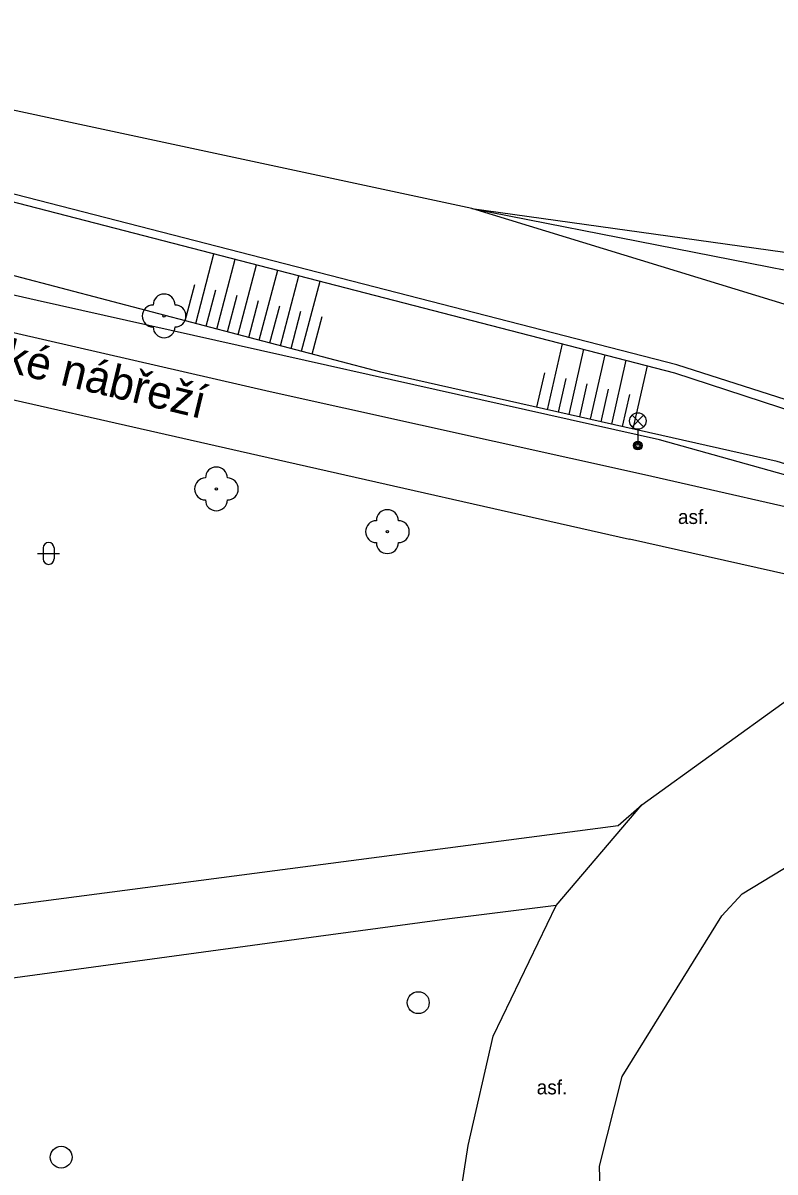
# Model space of a CAD drawing. Extents: x -598932 to -598196, y -1162207 to -1161504.
# Drawn here: x -598441.5 to -598407.2, y -1162126.2 to -1162073.7 of the extents above; entities that cross this region are included whole.
import ezdxf

# ---------------------------------------------------------------- set-up
doc = ezdxf.new("R2010")
doc.units = 0
for name, color, linetype in [('Level 22', 7, 'Continuous'), ('Level 27', 7, 'Continuous'), ('Level 33', 7, 'Continuous'), ('Level 36', 7, 'Continuous'), ('specificka linie pasportu komunikaci', 7, 'Continuous'), ('TM - chodniky - VP', 7, 'Continuous'), ('TM - hladina vodniho toku_ bazenu_ nadrze', 7, 'Continuous'), ('TM - horni hrana svahu', 7, 'Continuous'), ('TM - popis povrchu', 7, 'Continuous'), ('TM - rozhrani ploch obecne - VP', 7, 'Continuous'), ('TM - srafovani', 7, 'Continuous'), ('TM - zabradli - VP', 7, 'Continuous'), ('ulice', 7, 'Continuous')]:
    doc.layers.add(name, color=color, linetype=linetype)

msp = doc.modelspace()

# ---------------------------------------------------------------- linework, layer by layer
at = {"layer": 'Level 22'}
for centre in [(-598435.08, -1162087.12), (-598432.69, -1162095.02), (-598424.88, -1162096.97)]:
    msp.add_circle(centre, 0.05, dxfattribs=at)
for centre, start, end in [((-598435.08, -1162086.62), 0, 180), ((-598435.58, -1162087.12), 90, 270), ((-598434.58, -1162087.12), 270, 90), ((-598435.08, -1162087.62), 180, 0), ((-598432.69, -1162094.52), 0, 180), ((-598433.19, -1162095.02), 90, 270), ((-598432.19, -1162095.02), 270, 90), ((-598432.69, -1162095.52), 180, 0), ((-598424.88, -1162096.47), 0, 180), ((-598425.38, -1162096.97), 90, 270), ((-598424.38, -1162096.97), 270, 90), ((-598424.88, -1162097.47), 180, 0)]:
    msp.add_arc(centre, 0.5, start, end, dxfattribs=at)
at = {"layer": 'Level 27'}
for centre in [(-598423.47, -1162118.48), (-598439.78, -1162125.54)]:
    msp.add_circle(centre, 0.5, dxfattribs=at)
at = {"layer": 'Level 33'}
for p, q in [((-598413.705, -1162092.18), (-598413.175, -1162091.65)), ((-598413.705, -1162091.65), (-598413.175, -1162092.18)), ((-598413.44, -1162092.29), (-598413.44, -1162093.04))]:
    msp.add_line(p, q, dxfattribs=at)
for centre, radius in [((-598413.44, -1162091.915), 0.375), ((-598413.44, -1162093.04), 0.2), ((-598413.44, -1162093.04), 0.145), ((-598413.44, -1162093.04), 0.0876)]:
    msp.add_circle(centre, radius, dxfattribs=at)
at = {"layer": 'Level 36'}
for p, q in [((-598440.856, -1162097.966), (-598439.856, -1162097.966)), ((-598440.606, -1162097.716), (-598440.606, -1162098.216)), ((-598440.106, -1162097.716), (-598440.106, -1162098.216))]:
    msp.add_line(p, q, dxfattribs=at)
for centre, start, end in [((-598440.356, -1162097.716), 0, 180), ((-598440.356, -1162098.216), 180, 0)]:
    msp.add_arc(centre, 0.25, start, end, dxfattribs=at)
at = {"layer": 'specificka linie pasportu komunikaci'}
for points in [[(-598487.532, -1162108.589), (-598479.498, -1162112.819), (-598472.405, -1162116.75), (-598471.123, -1162117.306), (-598469.414, -1162117.605), (-598414.338, -1162110.384), (-598413.26, -1162109.45)], [(-598422.048, -1162114.648), (-598428.034, -1162115.454), (-598471.721, -1162121.408), (-598473.302, -1162120.724), (-598474.969, -1162119.742), (-598477.704, -1162118.16), (-598487.959, -1162112.648), (-598489.199, -1162112.135), (-598489.882, -1162112.05), (-598490.395, -1162112.306), (-598491.38, -1162119.1)], [(-598417.17, -1162114.04), (-598422.048, -1162114.648)]]:
    msp.add_lwpolyline(points, dxfattribs=at)
at = {"layer": 'TM - chodniky - VP'}
for points in [[(-598373.63, -1162107.44), (-598374.05, -1162106.27), (-598375.89, -1162104.49), (-598383.68, -1162101.64), (-598392.98, -1162098.93), (-598403.89, -1162096.47), (-598413.14, -1162094.37), (-598430.24, -1162090.58), (-598446.87, -1162086.77), (-598457.79, -1162084.42), (-598470.49, -1162081.8), (-598481.26, -1162079.85), (-598485.47, -1162079.11)], [(-598447.6, -1162089.67), (-598430.8, -1162093.47), (-598413.82, -1162097.31)], [(-598398.58, -1162100.79), (-598404.39, -1162099.43), (-598413.82, -1162097.31)], [(-598421.95, -1162129.89), (-598421.19, -1162125.01), (-598420.05, -1162120.01), (-598417.17, -1162114.04), (-598413.26, -1162109.45), (-598406.59, -1162104.64), (-598400.44, -1162101.93)], [(-598408.67, -1162113.51), (-598399.31, -1162107.84), (-598389.83, -1162107.69)], [(-598415.05, -1162130.72), (-598415.19, -1162125.95), (-598414.16, -1162121.85), (-598409.6, -1162114.51), (-598408.67, -1162113.51)]]:
    msp.add_lwpolyline(points, dxfattribs=at)
at = {"layer": 'TM - hladina vodniho toku_ bazenu_ nadrze'}
for points in [[(-598421.03, -1162082.21), (-598460.61, -1162073.74)], [(-598421.03, -1162082.21), (-598392.64, -1162086.17)]]:
    msp.add_lwpolyline(points, dxfattribs=at)
at = {"layer": 'TM - horni hrana svahu'}
msp.add_lwpolyline([(-598376.59, -1162101.31), (-598393.14, -1162097.78), (-598400.5, -1162095.77), (-598407.08, -1162093.76), (-598425.18, -1162089.68), (-598446.06, -1162084.2), (-598466.47, -1162079.89), (-598480.44, -1162076.62), (-598484.03, -1162075.37)], dxfattribs=at)
at = {"layer": 'TM - rozhrani ploch obecne - VP'}
for points in [[(-598443.98, -1162081.39), (-598411.77, -1162089.71), (-598392.63, -1162095.97), (-598376.59, -1162101.31)], [(-598392.49, -1162095.48), (-598411.66, -1162089.35), (-598443.91, -1162081.06)], [(-598367.77, -1162093.25), (-598387.57, -1162092.13), (-598394.34, -1162090.38), (-598421.03, -1162082.21)], [(-598421.03, -1162082.21), (-598393.12, -1162087.7), (-598367.77, -1162093.25)]]:
    msp.add_lwpolyline(points, dxfattribs=at)
at = {"layer": 'TM - srafovani'}
for points in [[(-598433.63, -1162087.46), (-598432.8, -1162084.28)], [(-598432.67, -1162087.72), (-598431.83, -1162084.53)], [(-598431.7, -1162087.97), (-598430.86, -1162084.78)], [(-598430.73, -1162088.22), (-598429.89, -1162085.03)], [(-598429.76, -1162088.48), (-598428.92, -1162085.28)], [(-598428.8, -1162088.73), (-598427.95, -1162085.53)], [(-598434.12, -1162087.34), (-598433.68, -1162085.68)], [(-598433.15, -1162087.59), (-598432.71, -1162085.92)], [(-598432.18, -1162087.84), (-598431.74, -1162086.17)], [(-598431.21, -1162088.1), (-598430.77, -1162086.41)], [(-598430.25, -1162088.35), (-598429.8, -1162086.66)], [(-598429.28, -1162088.6), (-598428.83, -1162086.9)], [(-598428.31, -1162088.86), (-598427.86, -1162087.15)], [(-598417.56, -1162091.4), (-598416.88, -1162088.39)], [(-598416.58, -1162091.62), (-598415.91, -1162088.64)], [(-598415.61, -1162091.84), (-598414.94, -1162088.89)], [(-598414.63, -1162092.06), (-598413.97, -1162089.14)], [(-598418.05, -1162091.29), (-598417.69, -1162089.72)], [(-598413.66, -1162092.28), (-598413, -1162089.39)], [(-598417.07, -1162091.51), (-598416.72, -1162089.97)], [(-598416.09, -1162091.73), (-598415.75, -1162090.22)], [(-598415.12, -1162091.95), (-598414.78, -1162090.46)], [(-598414.14, -1162092.17), (-598413.81, -1162090.71)]]:
    msp.add_lwpolyline(points, dxfattribs=at)
at = {"layer": 'TM - zabradli - VP'}
msp.add_lwpolyline([(-598370.51, -1162104.5), (-598390.34, -1162098.95), (-598412.45, -1162092.78), (-598440.87, -1162086.41), (-598474.92, -1162078.7)], dxfattribs=at)

# ---------------------------------------------------------------- texts
at = {"layer": 'TM - popis povrchu'}
for p in [(-598411.61, -1162096.62), (-598418.06, -1162122.67)]:
    msp.add_text('asf.', height=0.65, dxfattribs=at).set_placement(p)
at = {"layer": 'ulice'}
msp.add_text('Štýřické nábřeží', height=1.5, rotation=346.4101, dxfattribs=at).set_placement((-598447.346, -1162088.444))

doc.saveas('drawing.dxf')
